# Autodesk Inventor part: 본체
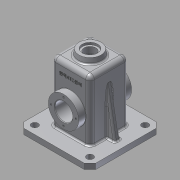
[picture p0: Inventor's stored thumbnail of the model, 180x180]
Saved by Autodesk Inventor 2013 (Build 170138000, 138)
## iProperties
Created: 2016-02
Part Number: 본체
Material: 알루미늄 6061
Document SubType Name: Modeling
Designer: user-11
Density: 2.71 g/cm^3
Mass: 939.134 g
Surface Area: 1045.46 cm^2
Volume: 346.544 cm^3
Author: user-11
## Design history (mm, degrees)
sketch "스케치1"
  geometry: L1 (-65, 65)-(65, 65); L2 (65, 65)-(65, -65); L3 (65, -65)-(-65, -65); L4 (-65, -65)-(-65, 65); 1 further point
  constraints: 8 end point, 2 parallel, 1 horizontal, 1 perpendicular
  dimensions: "d0" = 130 distance between parallel lines of L2 L4; "d3" = 130 distance between parallel lines of L3 L1; "d4" = 65 distance from line of point (0, 0) L1; "d5" = 65 distance from line of point (0, 0) L4
extrude "돌출1" new body sketch "스케치1" distance "d6" = 10; taper "d7" = 0 deg
chamfer "모따기1" distance "d8" = 10; stored, may be unused: second distance "d9" = 2, angle "d10" = 45 deg
sketch "스케치2"
  geometry: L1 (-65, 55)-(-65, -55) reference; L2 (-55, -65)-(55, -65) reference; L3 (65, -55)-(65, 55) reference; L4 (55, 65)-(-55, 65) reference; C1 r 6 at (-50, 50); C2 r 6 at (50, 50); C3 r 6 at (50, -50); C4 r 6 at (-50, -50); 1 further point
  constraints: 4 centre point
  dimensions: "d11" = 15 distance from line of L1 C1.centre; "d12" = 15 distance from line of L4 C1.centre; "d13" = 15 distance from line of L4 C2.centre; "d14" = 15 distance from line of L3 C2.centre; "d15" = 15 distance from line of L3 C3.centre; "d16" = 15 distance from line of L2 C3.centre; "d17" = 15 distance from line of L2 C4.centre; "d18" = 15 distance from line of L1 C4.centre; "d19" = 12 diameter of C1; "d20" = 12 diameter of C2; "d21" = 12 diameter of C3; "d22" = 12 diameter of C4
extrude "돌출2" cut sketch "스케치2" distance "d23" = 10; taper "d24" = 0 deg
sketch "스케치3"
  geometry: L1 (-35, 35)-(35, 35); L2 (35, 35)-(35, -35); L3 (35, -35)-(-35, -35); L4 (-35, -35)-(-35, 35); 1 further point
  constraints: 8 end point, 2 parallel, 1 horizontal, 1 perpendicular
  dimensions: "d25" = 70 distance between parallel lines of L2 L4; "d27" = 70 distance between parallel lines of L3 L1; "d28" = 35 distance from line of point (0, 0) L1; "d29" = 35 distance from line of point (0, 0) L4
extrude "돌출3" join sketch "스케치3" distance "d30" = 110; taper "d31" = 0 deg
feature "쉘1" dims "d32" = 5
sketch "스케치4"
  geometry: L1 (15.417, -30)-(15.417, -90) reference; L2 (75.417, -30)-(15.417, -30) reference; L3 (75.417, -90)-(75.417, -30) reference; L4 (15.417, -90)-(75.417, -90) reference; L5 (105.417, -14.583)-(105.417, -105.417) reference; L6 (0, 0)-(90.835, 0) reference; L7 (-14.583, -105.417)-(-14.583, -14.583) reference; L8 (90.835, -120)-(0, -120) reference; A1 r 11 centre (95.417, -110) between (105.417, -105.417) and (90.835, -120) reference; A2 r 11 centre (95.417, -10) between (90.835, 0) and (105.417, -14.583) reference; A3 r 11 centre (-4.583, -10) between (-14.583, -14.583) and (0, 0) reference; A4 r 11 centre (-4.583, -110) between (0, -120) and (-14.583, -105.417) reference; 1 further point
extrude "돌출4" join sketch "스케치4" distance "d33" = 5; taper "d34" = 0 deg
fillet "모깎기1" dims "d35" = 8, "d36" = 3
node "작업 평면1"
sketch "스케치5"
  geometry: C1 r 20 at (0, 0); 1 further point
  constraints: 1 centre point, 1 coincident
  dimensions: "d38" = 40 diameter of C1
extrude "돌출5" join sketch "스케치5" stored distance "d40" = 5; taper "d41" = 10 deg
sketch "스케치6"
  geometry: C1 r 20 at (0, 0) reference; C2 r 14 at (0, 0)
  constraints: 1 centre point, 1 coincident
  dimensions: "d42" = 28 diameter of C2
extrude "돌출6" cut sketch "스케치6" distance "d44" = 4; taper "d45" = 0 deg
sketch "스케치7"
  geometry: C1 r 14 at (0, 0) reference; C2 r 10.5 at (0, 0)
  constraints: 1 centre point, 1 coincident
  dimensions: "d46" = 21 diameter of C2
extrude "돌출7" cut sketch "스케치7" stored distance "d48" = 4; taper "d49" = 0 deg
sketch "스케치8"
  geometry: C1 r 27.5 at (27, 45); 1 further point
  constraints: 1 centre point
  dimensions: "d50" = 55 diameter of C1; "d52" = 0 horizontal distance of point (27, -10) C1.centre; "d53" = 55 distance of point (27, -10) C1.centre
extrude "돌출8" join sketch "스케치8" distance "d54" = 13; taper "d55" = 0 deg
sketch "스케치9"
  geometry: C1 r 27.5 at (27, -55); 1 further point
  constraints: 1 centre point
  dimensions: "d56" = 55 diameter of C1; "d58" = 0 horizontal distance of point (27, 0) C1.centre; "d59" = 55 distance of point (27, 0) C1.centre
extrude "돌출9" join sketch "스케치9" distance "d60" = 7; taper "d61" = -45 deg
sketch "스케치10"
  geometry: C1 r 27.5 at (0, 0) reference; C2 r 16 at (0, 0); 1 further point
  constraints: 1 centre point, 1 coincident
  dimensions: "d62" = 32 diameter of C2
extrude "돌출10" cut sketch "스케치10" stored distance "d64" = 7; taper "d65" = 0 deg
sketch "스케치11"
  geometry: C1 r 16 at (0, 0) reference; C2 r 2 at (0, 22.5); 1 further point
  constraints: 1 centre point
  dimensions: "d66" = 4 diameter of C2; "d68" = 0 horizontal distance of C1.centre C2.centre; "d69" = 22.5 distance of C1.centre C2.centre
hole "구멍1" sketch "스케치11" at (0, 22.5) diameter "d70" = 3.242; stored, may be unused: countersink angle "d74" = 90 deg, drill point angle "d76" = 118 deg; dims "d71" = 8, "d72" = 4, "d73" = 2, "d75" = 10
sketch "스케치12"
  geometry: L1 (-35, 10)-(-35, 112) reference; L2 (55, 10)-(-55, 10) reference; L3 (-65, 10)-(-55, 10) reference; L4 (-35, 95.069)-(-50, 10); L5 (-65, 0)-(-65, 10) reference; 1 further point
  constraints: 2 end point, 2 point on line
  dimensions: "d80" = 15 distance from line of L5 L4.end; "d82" = 10 deg angle of L4 L5
feature "리브1" sketch "스케치12" dims "d83" = 1, "d84" = 10, "d85" = 0, "d86" = 0, "d87" = 1, "d88" = 1
sketch "스케치13"
  geometry: L1 (5.471, -8.998)-(48.529, -8.998); L2 (48.529, -8.998)-(48.529, -15.002); L3 (48.529, -15.002)-(5.471, -15.002); L4 (5.471, -15.002)-(5.471, -8.998); L5 (5.471, -12)-(48.529, -12); L6 (27, -8.998)-(27, -15.002); L7 (7, 18)-(47, 18) reference; L8 (62, -102)-(62, 0) reference; 1 further point
  constraints: 4 end point, 4 midpoint, 2 other
  dimensions: "d89" = 30 distance between parallel lines of L5 L7; "d90" = 35 distance between parallel lines of L8 L6
extrude "돌출11" join sketch "스케치13" distance "d91" = 0.5; taper "d92" = 0 deg
fillet "모깎기2" dims "d93" = 0.5, "d94" = 3
fillet "모깎기3" dims "d95" = 3
chamfer "모따기2" distance "d96" = 1; stored, may be unused: second distance "d97" = 2, angle "d98" = 45 deg
node "솔리드1"
pattern_circular "원형 패턴1" dims angle "d78" = 360 deg
mirror "대칭1"
mirror "대칭2"
